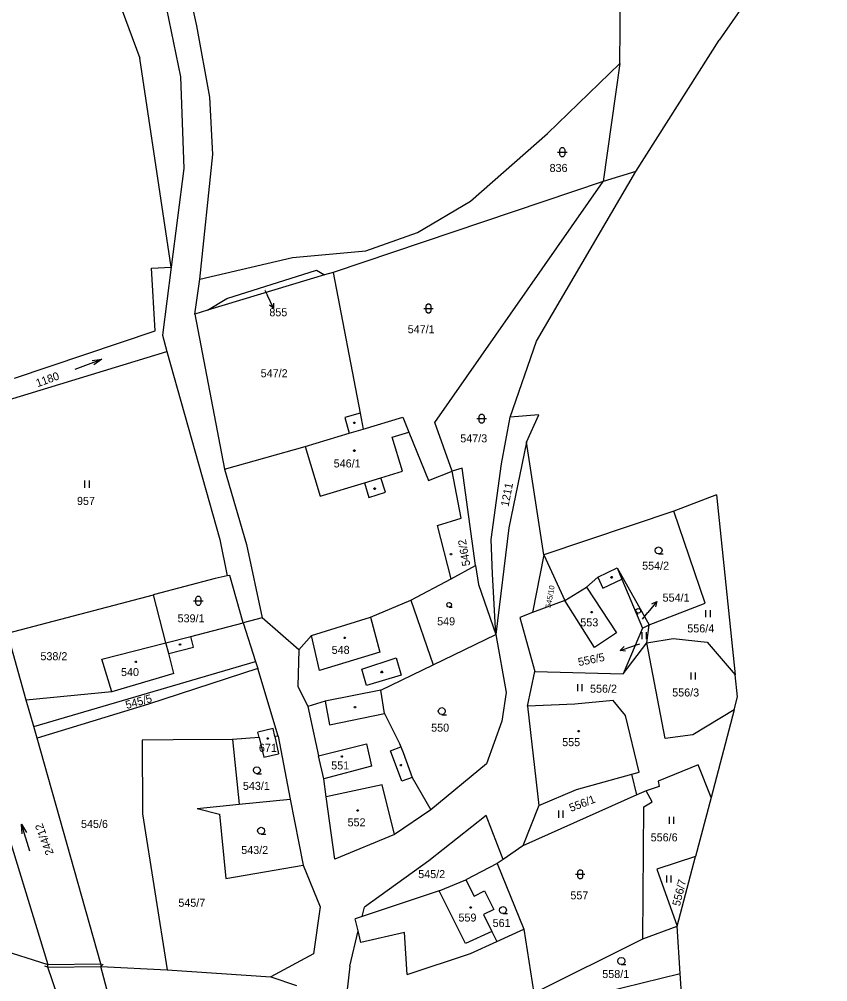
# Model space of a CAD drawing. Extents: x -812394 to -807601, y -1013097 to -1009266.
# Drawn here: x -809003.5 to -808832.6, y -1011690.8 to -1011487.2 of the extents above; entities that cross this region are included whole.
import ezdxf

# ---------------------------------------------------------------- set-up
doc = ezdxf.new("R2010")
doc.units = 0
for name, color, linetype in [('Default', 7, 'Continuous'), ('KN_HRANICE', 7, 'Continuous'), ('KN_KULTURY', 7, 'Continuous'), ('KN_PARCELY', 7, 'Continuous'), ('KN_SLUCKY', 7, 'Continuous')]:
    doc.layers.add(name, color=color, linetype=linetype)

# ---------------------------------------------------------------- blocks, each defined once
blk = doc.blocks.new('10292')
at = {"layer": 'Default'}
blk.add_line((0, 3), (0, 0), dxfattribs=at)
blk.add_lwpolyline([(-0.5, 2), (0, 3), (0.5, 2)], dxfattribs=at)
blk = doc.blocks.new('4201')
at = {"layer": 'Default'}
blk.add_line((0, 0), (-0.5, -0.5), dxfattribs=at)
blk = doc.blocks.new('304')
at = {"layer": 'Default'}
blk.add_lwpolyline([(0, 0), (-0.38, 0.1), (-0.65, 0.37), (-0.75, 0.74), (-0.65, 1.11), (-0.38, 1.38), (-0.01, 1.48), (0.36, 1.38), (0.63, 1.11), (0.73, 0.73), (0.63, 0.35), (0.36, 0.08), (-0.02, -0.02), (0.98, -0.02)], dxfattribs=at)
blk = doc.blocks.new('306')
at = {"layer": 'Default'}
for p, q in [((-0.5, 1.5), (-0.5, 0)), ((0.5, 0), (0.5, 1.5))]:
    blk.add_line(p, q, dxfattribs=at)
blk = doc.blocks.new('316')
at = {"layer": 'Default'}
for points in [[(-1, 1), (0.27, 1), (1, 1)], [(-0.5, 1.5), (-0.4, 1.79), (-0.15, 1.97), (0.16, 1.97), (0.41, 1.79), (0.51, 1.5), (0.51, 0.5), (0.41, 0.21), (0.16, 0.03), (-0.15, 0.03), (-0.4, 0.21), (-0.5, 0.5), (-0.5, 1.5)]]:
    blk.add_lwpolyline(points, dxfattribs=at)
blk = doc.blocks.new('NAHRADNI_SYMBOL')
at = {"layer": 'Default'}
blk.add_lwpolyline([(0.09, 0.15), (0.18, 0), (0.09, -0.15), (-0.09, -0.15), (-0.18, 0), (-0.09, 0.15), (0.09, 0.15)], dxfattribs=at)
blk = doc.blocks.new('802')
at = {"layer": 'Default'}
blk.add_line((-3, 0), (3, 0), dxfattribs=at)
blk.add_lwpolyline([(1, 0.5), (3, 0), (1, -0.5)], dxfattribs=at)
blk = doc.blocks.new('402')
at = {"layer": 'Default'}
blk.add_lwpolyline([(0.09, 0.15), (0.18, 0), (0.09, -0.15), (-0.09, -0.15), (-0.18, 0), (-0.09, 0.15), (0.09, 0.15)], dxfattribs=at)

msp = doc.modelspace()

# ---------------------------------------------------------------- linework, layer by layer
at = {"layer": 'KN_HRANICE'}
for p, q in [((-808965.96, -1011488.59), (-808970.28, -1011469.05)), ((-808974.44, -1011475.12), (-808969.45, -1011499.37)), ((-808963.26, -1011503.69), (-808965.96, -1011488.59)), ((-808873.2, -1011519.41), (-808855.58, -1011491.65)), ((-808971.42, -1011539.63), (-808978.04, -1011495.45)), ((-808891.84, -1011511.36), (-808876.58, -1011496.57)), ((-808876.58, -1011496.57), (-808880.08, -1011521.57)), ((-808969.45, -1011499.37), (-808968.75, -1011518.78)), ((-808962.56, -1011515.81), (-808963.26, -1011503.69)), ((-808908.15, -1011525.71), (-808891.84, -1011511.36)), ((-808965.32, -1011542.2), (-808962.56, -1011515.81)), ((-808968.75, -1011518.78), (-808971.42, -1011539.63)), ((-808894.18, -1011555.33), (-808873.2, -1011519.41)), ((-808873.2, -1011519.41), (-808880.08, -1011521.57)), ((-808880.08, -1011521.57), (-808937.15, -1011540.75)), ((-808915.66, -1011572.49), (-808880.08, -1011521.57)), ((-808919.33, -1011532.32), (-808908.15, -1011525.71)), ((-808930.24, -1011536.22), (-808919.33, -1011532.32)), ((-808945.75, -1011537.6), (-808930.24, -1011536.22)), ((-808965.32, -1011542.2), (-808945.75, -1011537.6)), ((-808975.53, -1011539.84), (-808971.42, -1011539.63)), ((-808974.75, -1011553.11), (-808975.53, -1011539.84)), ((-808971.42, -1011539.63), (-808973.26, -1011554.04)), ((-808966.39, -1011549.59), (-808965.32, -1011542.2)), ((-808939.01, -1011541.31), (-808963.72, -1011548.78)), ((-808937.15, -1011540.75), (-808939.01, -1011541.31)), ((-808937.15, -1011540.75), (-808931.47, -1011570.52)), ((-808963.72, -1011548.78), (-808966.39, -1011549.59)), ((-808966.39, -1011549.59), (-808960.16, -1011582.4)), ((-809004.54, -1011563.13), (-808974.75, -1011553.11)), ((-808973.26, -1011554.04), (-808972.29, -1011557.49)), ((-808899.78, -1011571.39), (-808894.18, -1011555.33)), ((-809001.64, -1011566.41), (-808972.29, -1011557.49)), ((-808972.29, -1011557.49), (-808961.13, -1011597.23)), ((-809019.32, -1011571.78), (-809001.64, -1011566.41)), ((-808931.47, -1011570.52), (-808934.7, -1011571.43)), ((-808931.47, -1011570.52), (-808930.83, -1011573.88)), ((-808893.7, -1011570.91), (-808899.78, -1011571.39)), ((-808896.31, -1011576.65), (-808893.7, -1011570.91)), ((-808934.7, -1011571.43), (-808933.76, -1011574.76)), ((-808930.83, -1011573.88), (-808922.44, -1011571.37)), ((-808922.44, -1011571.37), (-808921.16, -1011574.54)), ((-808911.99, -1011582.79), (-808915.66, -1011572.49)), ((-808901.58, -1011581.26), (-808899.78, -1011571.39)), ((-808943.1, -1011577.55), (-808933.76, -1011574.76)), ((-808921.16, -1011574.54), (-808917.01, -1011584.77)), ((-808896.31, -1011576.65), (-808900.05, -1011594.78)), ((-808892.65, -1011600.49), (-808896.31, -1011576.65)), ((-808960.16, -1011582.4), (-808943.1, -1011577.55)), ((-808903.77, -1011597.26), (-808901.58, -1011581.26)), ((-808960.16, -1011582.4), (-808955.5, -1011598.34)), ((-808917.01, -1011584.77), (-808911.99, -1011582.79)), ((-808909.89, -1011582.19), (-808911.99, -1011582.79)), ((-808910.08, -1011592.77), (-808911.99, -1011582.79)), ((-808907.08, -1011602.78), (-808909.89, -1011582.19)), ((-808856.13, -1011587.82), (-808865.17, -1011591.23)), ((-808856.13, -1011587.82), (-808852.21, -1011625.86)), ((-808865.17, -1011591.23), (-808892.65, -1011600.49)), ((-808858.54, -1011610.68), (-808865.17, -1011591.23)), ((-808915.15, -1011594.3), (-808910.08, -1011592.77)), ((-808912.24, -1011605.55), (-808915.15, -1011594.3)), ((-808900.05, -1011594.78), (-808902.81, -1011617.34)), ((-808961.13, -1011597.23), (-808959.58, -1011604.96)), ((-808903.49, -1011604.54), (-808903.77, -1011597.26)), ((-808955.5, -1011598.34), (-808952.16, -1011613.79)), ((-808892.65, -1011600.49), (-808895.03, -1011612.7)), ((-808892.65, -1011600.49), (-808888.21, -1011610.12)), ((-808912.24, -1011605.55), (-808907.08, -1011602.78)), ((-808907.08, -1011602.78), (-808906.47, -1011606.8)), ((-808881.24, -1011605.2), (-808877.14, -1011603.27)), ((-808877.14, -1011603.27), (-808870.36, -1011615.27)), ((-808877.14, -1011603.27), (-808876.15, -1011605.63)), ((-808962.09, -1011605.51), (-808974.9, -1011608.87)), ((-808959.58, -1011604.96), (-808962.09, -1011605.51)), ((-808959, -1011604.83), (-808959.58, -1011604.96)), ((-808956.17, -1011614.89), (-808959, -1011604.83)), ((-808920.72, -1011610.1), (-808912.24, -1011605.55)), ((-808902.81, -1011617.34), (-808903.49, -1011604.54)), ((-808883.6, -1011607.34), (-808881.24, -1011605.2)), ((-808876.15, -1011605.63), (-808871.82, -1011615.97)), ((-808906.47, -1011606.8), (-808902.81, -1011617.34)), ((-808888.21, -1011610.12), (-808883.6, -1011607.34)), ((-809006.01, -1011617.04), (-808975.11, -1011608.93)), ((-808974.9, -1011608.87), (-808975.11, -1011608.93)), ((-808972.5, -1011619.08), (-808975.11, -1011608.93)), ((-808929.24, -1011613.67), (-808920.72, -1011610.1)), ((-808920.72, -1011610.1), (-808916.02, -1011623.74)), ((-808888.21, -1011610.12), (-808895.03, -1011612.7)), ((-808870.36, -1011615.27), (-808858.54, -1011610.68)), ((-808952.16, -1011613.79), (-808956.17, -1011614.89)), ((-808944.42, -1011620.59), (-808952.16, -1011613.79)), ((-808941.71, -1011617.53), (-808929.24, -1011613.67)), ((-808895.03, -1011612.7), (-808897.71, -1011613.71)), ((-808897.71, -1011613.71), (-808894.56, -1011625.13)), ((-808967.27, -1011617.74), (-808956.17, -1011614.89)), ((-808956.17, -1011614.89), (-808953.55, -1011623.03)), ((-808871.82, -1011615.97), (-808875.9, -1011625.68)), ((-808871.82, -1011615.97), (-808870.36, -1011615.27)), ((-808870.85, -1011619.12), (-808870.36, -1011615.27)), ((-809002.01, -1011631.2), (-809006.01, -1011617.04)), ((-808972.5, -1011619.08), (-808967.27, -1011617.74)), ((-808941.71, -1011617.53), (-808944.42, -1011620.59)), ((-808916.02, -1011623.74), (-808902.81, -1011617.34)), ((-808902.81, -1011617.34), (-808900.58, -1011629.58)), ((-808986.05, -1011622.56), (-808972.5, -1011619.08)), ((-808875.9, -1011625.68), (-808870.85, -1011619.12)), ((-808870.85, -1011619.12), (-808865.28, -1011618.21)), ((-808866.98, -1011639.31), (-808870.85, -1011619.12)), ((-808865.28, -1011618.21), (-808858.15, -1011618.94)), ((-808858.15, -1011618.94), (-808852.21, -1011625.86)), ((-808944.42, -1011620.59), (-808944.61, -1011628.26)), ((-809000.43, -1011636.79), (-808953.55, -1011623.03)), ((-808983.95, -1011629.44), (-808986.05, -1011622.56)), ((-808953.55, -1011623.03), (-808953.09, -1011624.56)), ((-808927.11, -1011629.12), (-808916.02, -1011623.74)), ((-808953.09, -1011624.56), (-808976.16, -1011632.06)), ((-808948.82, -1011638.83), (-808953.09, -1011624.56)), ((-808896.11, -1011632.48), (-808894.56, -1011625.13)), ((-808894.56, -1011625.13), (-808875.9, -1011625.68)), ((-808851.7, -1011630.55), (-808852.21, -1011625.86)), ((-808944.61, -1011628.26), (-808942.49, -1011632.58)), ((-809015.5, -1011628.37), (-808997.45, -1011687.11)), ((-808983.95, -1011629.44), (-809002.01, -1011631.2)), ((-808927.11, -1011629.12), (-808938.89, -1011631.46)), ((-808926.34, -1011634.03), (-808927.11, -1011629.12)), ((-808900.58, -1011629.58), (-808901.53, -1011635.69)), ((-809000.43, -1011636.79), (-809002.01, -1011631.2)), ((-808976.16, -1011632.06), (-808999.74, -1011639.23)), ((-808938.89, -1011631.46), (-808942.49, -1011632.58)), ((-808886.06, -1011632.1), (-808896.11, -1011632.48)), ((-808877.99, -1011631.31), (-808886.06, -1011632.1)), ((-808875.36, -1011634.48), (-808877.99, -1011631.31)), ((-808852.42, -1011633.29), (-808851.7, -1011630.55)), ((-808942.49, -1011632.58), (-808940.26, -1011643.02)), ((-808926.34, -1011634.03), (-808923.15, -1011640.39)), ((-808896.11, -1011632.48), (-808893.67, -1011653.49)), ((-808852.42, -1011633.29), (-808861.12, -1011638.59)), ((-808852.42, -1011633.29), (-808857.31, -1011651.79)), ((-808901.53, -1011635.69), (-808904.76, -1011644.68)), ((-808872.48, -1011646.42), (-808875.36, -1011634.48)), ((-808999.74, -1011639.23), (-809000.43, -1011636.79)), ((-808949.87, -1011637.24), (-808953.07, -1011637.96)), ((-808952.81, -1011639.12), (-808953.07, -1011637.96)), ((-808949.52, -1011638.88), (-808949.87, -1011637.24)), ((-808986.27, -1011686.97), (-808999.74, -1011639.23)), ((-808970.95, -1011639.63), (-808977.55, -1011639.69)), ((-808977.55, -1011639.69), (-808977.45, -1011655.27)), ((-808958.46, -1011639.52), (-808970.95, -1011639.63)), ((-808952.81, -1011639.12), (-808958.46, -1011639.52)), ((-808958.46, -1011639.52), (-808957.03, -1011653.25)), ((-808952.81, -1011639.12), (-808951.84, -1011643.29)), ((-808948.82, -1011638.83), (-808949.52, -1011638.88)), ((-808949.52, -1011638.88), (-808948.71, -1011642.58)), ((-808948.82, -1011638.83), (-808946.22, -1011652.17)), ((-808923.15, -1011640.39), (-808922.85, -1011641.1)), ((-808861.12, -1011638.59), (-808866.98, -1011639.31)), ((-808922.85, -1011641.1), (-808922.34, -1011642.28)), ((-808922.34, -1011642.28), (-808920.49, -1011647.59)), ((-808951.84, -1011643.29), (-808948.71, -1011642.58)), ((-808939.13, -1011647.83), (-808940.26, -1011643.02)), ((-808904.76, -1011644.68), (-808916.52, -1011654.39)), ((-808874.08, -1011646.85), (-808872.48, -1011646.42)), ((-808860.02, -1011644.93), (-808868.49, -1011648.39)), ((-808857.31, -1011651.79), (-808860.02, -1011644.93)), ((-808938.61, -1011651.69), (-808939.13, -1011647.83)), ((-808920.49, -1011647.59), (-808916.52, -1011654.39)), ((-808885.73, -1011650.13), (-808874.08, -1011646.85)), ((-808872.98, -1011651.23), (-808874.08, -1011646.85)), ((-808868.49, -1011648.39), (-808868.26, -1011649.51)), ((-808926.82, -1011649.1), (-808938.61, -1011651.69)), ((-808924.23, -1011659.63), (-808926.82, -1011649.1)), ((-808893.67, -1011653.49), (-808885.73, -1011650.13)), ((-808871.05, -1011650.4), (-808872.98, -1011651.23)), ((-808868.26, -1011649.51), (-808871.05, -1011650.4)), ((-808869.78, -1011652.71), (-808871.05, -1011650.4)), ((-808957.03, -1011653.25), (-808946.22, -1011652.17)), ((-808946.22, -1011652.17), (-808943.5, -1011666.11)), ((-808936.84, -1011664.82), (-808938.61, -1011651.69)), ((-808872.98, -1011651.23), (-808897.06, -1011662.04)), ((-808857.31, -1011651.79), (-808860.61, -1011664.31)), ((-808965.93, -1011654.13), (-808957.03, -1011653.25)), ((-808965.93, -1011654.13), (-808961.16, -1011655.32)), ((-808916.52, -1011654.39), (-808924.23, -1011659.63)), ((-808893.67, -1011653.49), (-808897.06, -1011662.04)), ((-808871.71, -1011681.7), (-808871.48, -1011653.76)), ((-808871.48, -1011653.76), (-808869.78, -1011652.71)), ((-808977.45, -1011655.27), (-808972.23, -1011688.25)), ((-808961.16, -1011655.32), (-808959.88, -1011668.96)), ((-808904.82, -1011655.59), (-808916.94, -1011665.21)), ((-808901.27, -1011664.95), (-808904.82, -1011655.59)), ((-808924.23, -1011659.63), (-808936.84, -1011664.82)), ((-808897.06, -1011662.04), (-808901.27, -1011664.95)), ((-808860.61, -1011664.31), (-808868.75, -1011667)), ((-808864.5, -1011679.01), (-808860.61, -1011664.31)), ((-808959.88, -1011668.96), (-808943.5, -1011666.11)), ((-808943.5, -1011666.11), (-808939.94, -1011674.92)), ((-808916.94, -1011665.21), (-808930.55, -1011674.98)), ((-808902.48, -1011665.78), (-808909.14, -1011669.19)), ((-808901.27, -1011664.95), (-808902.48, -1011665.78)), ((-808902.48, -1011665.78), (-808896.85, -1011679.68)), ((-808868.75, -1011667), (-808864.5, -1011679.01)), ((-808914.74, -1011671.58), (-808909.14, -1011669.19)), ((-808909.14, -1011669.19), (-808907.39, -1011672.67)), ((-808914.74, -1011671.58), (-808931.05, -1011676.97)), ((-808907.39, -1011672.67), (-808905.21, -1011671.57)), ((-808905.21, -1011671.57), (-808903.24, -1011675.49)), ((-808939.94, -1011674.92), (-808941.31, -1011684.84)), ((-808931.05, -1011676.97), (-808930.55, -1011674.98)), ((-808931.05, -1011676.97), (-808932.49, -1011677.45)), ((-808903.24, -1011675.49), (-808905.42, -1011676.59)), ((-808905.42, -1011676.59), (-808903.63, -1011680.15)), ((-808931.89, -1011680.04), (-808932.49, -1011677.45)), ((-808871.71, -1011681.7), (-808864.5, -1011679.01)), ((-808863.84, -1011689.06), (-808864.5, -1011679.01)), ((-808933.67, -1011687.5), (-808931.89, -1011680.04)), ((-808931.32, -1011682.47), (-808931.89, -1011680.04)), ((-808922.12, -1011680.38), (-808931.32, -1011682.47)), ((-808921.53, -1011689.24), (-808922.12, -1011680.38)), ((-808903.63, -1011680.15), (-808902.57, -1011682.28)), ((-808902.57, -1011682.28), (-808896.85, -1011679.68)), ((-808896.85, -1011679.68), (-808894.75, -1011693.18)), ((-809014.11, -1011681.87), (-808997.45, -1011687.11)), ((-808908.14, -1011684.83), (-808902.57, -1011682.28)), ((-808894.75, -1011693.18), (-808871.71, -1011681.7)), ((-808941.31, -1011684.84), (-808950.35, -1011689.74)), ((-808921.53, -1011689.24), (-808908.14, -1011684.83)), ((-808997.45, -1011687.11), (-808986.27, -1011686.97)), ((-808997.44, -1011687.71), (-808997.45, -1011687.11)), ((-808986.27, -1011686.97), (-808986.26, -1011687.57)), ((-808995.44, -1011693.68), (-808997.44, -1011687.71)), ((-808986.26, -1011687.57), (-808972.23, -1011688.25)), ((-808984.63, -1011693.65), (-808986.26, -1011687.57)), ((-808972.23, -1011688.25), (-808950.35, -1011689.74)), ((-808933.67, -1011687.5), (-808934.28, -1011693.03)), ((-808879.89, -1011692.95), (-808863.84, -1011689.06)), ((-808861.85, -1011719.28), (-808863.84, -1011689.06)), ((-808950.35, -1011689.74), (-808944.94, -1011691.54))]:
    msp.add_line(p, q, dxfattribs=at)
for points in [[(-808876.58, -1011496.57), (-808876.5, -1011489.14), (-808876.71, -1011462.42), (-808881.55, -1011440.6), (-808894.69, -1011432.01), (-808924.68, -1011432.91), (-808919.61, -1011417.84), (-808910.04, -1011399.6), (-808897.42, -1011390.94), (-808865.7, -1011380.51), (-808873.42, -1011358.96)], [(-809039.69, -1011388.93), (-809024.1, -1011392.16), (-809015.94, -1011401.01), (-809005.51, -1011425.71), (-808989.67, -1011464.02), (-808978.04, -1011495.45)], [(-808777.29, -1011424.22), (-808793.61, -1011431.29), (-808814.66, -1011442.69), (-808827.8, -1011455.19), (-808842.35, -1011472.52), (-808855.58, -1011491.65)], [(-808963.72, -1011548.78), (-808959.65, -1011546.28), (-808940.7, -1011540.29), (-808939.01, -1011541.31)]]:
    msp.add_lwpolyline(points, dxfattribs=at)
at = {"layer": 'KN_PARCELY'}
for p, q in [((-808951.59, -1011544.55), (-808951.07, -1011545.65)), ((-808871.82, -1011614.11), (-808870.68, -1011612.71)), ((-808872.46, -1011619.39), (-808873.64, -1011619.77))]:
    msp.add_line(p, q, dxfattribs=at)
at = {"layer": 'KN_SLUCKY'}
for p, q in [((-808933.76, -1011574.76), (-808930.83, -1011573.88)), ((-808924.71, -1011575.62), (-808921.16, -1011574.54)), ((-808922.53, -1011582.8), (-808924.71, -1011575.62)), ((-808943.1, -1011577.55), (-808939.94, -1011588.09)), ((-808927.09, -1011584.18), (-808922.53, -1011582.8)), ((-808939.94, -1011588.09), (-808930.53, -1011585.23)), ((-808930.53, -1011585.23), (-808927.09, -1011584.18)), ((-808930.53, -1011585.23), (-808929.61, -1011588.4)), ((-808926.07, -1011587.22), (-808927.09, -1011584.18)), ((-808929.61, -1011588.4), (-808926.07, -1011587.22)), ((-808881.24, -1011605.2), (-808880.15, -1011607.51)), ((-808880.15, -1011607.51), (-808876.15, -1011605.63)), ((-808883.6, -1011607.34), (-808877.26, -1011617.01)), ((-808881.92, -1011620.12), (-808888.21, -1011610.12)), ((-808929.24, -1011613.67), (-808927.28, -1011621.11)), ((-808966.69, -1011620.05), (-808967.27, -1011617.74)), ((-808940.08, -1011624.95), (-808941.71, -1011617.53)), ((-808877.26, -1011617.01), (-808881.92, -1011620.12)), ((-808971.91, -1011621.37), (-808972.5, -1011619.08)), ((-808971.91, -1011621.37), (-808966.69, -1011620.05)), ((-808970.84, -1011625.57), (-808971.91, -1011621.37)), ((-808927.28, -1011621.11), (-808940.08, -1011624.95)), ((-808931.14, -1011624.64), (-808923.87, -1011622.27)), ((-808923.87, -1011622.27), (-808922.78, -1011625.91)), ((-808970.84, -1011625.57), (-808983.95, -1011629.44)), ((-808930.11, -1011628.1), (-808931.14, -1011624.64)), ((-808922.78, -1011625.91), (-808930.11, -1011628.1)), ((-808938.89, -1011631.46), (-808937.94, -1011636.42)), ((-808937.94, -1011636.42), (-808926.34, -1011634.03)), ((-808940.26, -1011643.02), (-808930.1, -1011640.49)), ((-808930.1, -1011640.49), (-808929.06, -1011645.16)), ((-808925.04, -1011641.91), (-808922.85, -1011641.1)), ((-808922.67, -1011648.35), (-808925.04, -1011641.91)), ((-808929.06, -1011645.16), (-808939.13, -1011647.83)), ((-808920.49, -1011647.59), (-808922.67, -1011648.35)), ((-808909.19, -1011682.69), (-808914.74, -1011671.58)), ((-808903.63, -1011680.15), (-808909.19, -1011682.69)), ((-808997.44, -1011687.71), (-808986.26, -1011687.57))]:
    msp.add_line(p, q, dxfattribs=at)

# ---------------------------------------------------------------- block references
at = {"layer": 'KN_KULTURY'}
for name, p in [('316', (-808888.73, -1011516.33)), ('316', (-808917.01, -1011549.41)), ('316', (-808905.78, -1011572.69)), ('402', (-808932.7, -1011572.58)), ('402', (-808932.71, -1011578.46)), ('306', (-808989.19, -1011586.3)), ('402', (-808928.41, -1011586.49)), ('304', (-808868.4, -1011600.29)), ('NAHRADNI_SYMBOL', (-808912.27, -1011600.35)), ('402', (-808878.33, -1011605.25)), ('316', (-808965.66, -1011611.21)), ('402', (-808882.54, -1011612.61)), ('306', (-808857.95, -1011613.7)), ('402', (-808934.71, -1011618.05)), ('306', (-808871.45, -1011618.36)), ('402', (-808969.54, -1011619.45)), ('402', (-808978.86, -1011623.12)), ('402', (-808926.88, -1011625.27)), ('306', (-808861.1, -1011626.85)), ('306', (-808885.05, -1011629.35)), ('402', (-808932.54, -1011632.7)), ('304', (-808914.2, -1011634.28)), ('NAHRADNI_SYMBOL', (-808885.27, -1011637.77)), ('402', (-808950.98, -1011639.31)), ('402', (-808935.32, -1011643.16)), ('304', (-808953.28, -1011646.78)), ('402', (-808922.86, -1011644.95)), ('NAHRADNI_SYMBOL', (-808931.98, -1011654.57)), ('306', (-808889.07, -1011656.09)), ('306', (-808865.65, -1011657.4)), ('304', (-808952.38, -1011659.58)), ('316', (-808884.95, -1011669.06)), ('306', (-808866.25, -1011669.81)), ('402', (-808908.09, -1011675.07)), ('304', (-808901.27, -1011676.35)), ('304', (-808876.26, -1011687.13))]:
    msp.add_blockref(name, p, dxfattribs=at)
for p, rotation in [((-808988.88, -1011560.18), 20.511889), ((-809002.13, -1011660.29), 106.913925)]:
    msp.add_blockref('802', p, dxfattribs=dict(at, rotation=rotation))
at = {"layer": 'KN_KULTURY', "xscale": 0.67, "yscale": 0.67}
msp.add_blockref('304', (-808912.65, -1011611.56), dxfattribs=at)
at = {"layer": 'KN_KULTURY', "xscale": 0.67, "yscale": 0.6699999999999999, "rotation": -59.598228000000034}
msp.add_blockref('304', (-808873.1, -1011612.57), dxfattribs=at)
at = {"layer": 'KN_PARCELY'}
for p, rotation in [((-808951.07, -1011545.65), -154.30815200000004), ((-808870.68, -1011612.71), -39.25822599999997), ((-808873.64, -1011619.77), 107.830657)]:
    msp.add_blockref('10292', p, dxfattribs=dict(at, rotation=rotation))
at = {"layer": 'KN_SLUCKY'}
for p, rotation in [((-808997.44, -1011687.71), -65.90076400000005), ((-808986.26, -1011687.57), 179.33579)]:
    msp.add_blockref('4201', p, dxfattribs=dict(at, rotation=rotation))

# ---------------------------------------------------------------- texts
at = {"layer": 'KN_PARCELY'}
for s, height, p in [('836', 1.7, (-808891.43, -1011519.52)), ('855', 1.7, (-808950.65, -1011550.04)), ('547/1', 1.7, (-808921.41, -1011553.63)), ('547/2', 1.7, (-808952.48, -1011562.94)), ('547/3', 1.7, (-808910.3, -1011576.71)), ('546/1', 1.7, (-808937.05, -1011582.01)), ('957', 1.7, (-808991.3, -1011589.94)), ('554/2', 1.7, (-808871.87, -1011603.64)), ('554/1', 1.7, (-808867.54, -1011610.39)), ('539/1', 1.7, (-808970.04, -1011614.77)), ('549', 1.7, (-808915.19, -1011615.4)), ('553', 1.7, (-808884.93, -1011615.62)), ('554/1', 0.1, (-808872.05, -1011614.11)), ('556/4', 1.7, (-808862.32, -1011616.9)), ('548', 1.7, (-808937.48, -1011621.44)), ('556/5', 0.1, (-808872.7, -1011619.39)), ('538/2', 1.7, (-808999.03, -1011622.78)), ('540', 1.7, (-808982, -1011626.13)), ('556/2', 1.7, (-808882.88, -1011629.65)), ('556/3', 1.7, (-808865.51, -1011630.45)), ('550', 1.7, (-808916.46, -1011637.89)), ('671', 1.7, (-808952.86, -1011642.16)), ('555', 1.7, (-808888.77, -1011640.95)), ('551', 1.7, (-808937.58, -1011645.88)), ('543/1', 1.7, (-808956.24, -1011650.2)), ('545/6', 1.7, (-808990.45, -1011658.25)), ('552', 1.7, (-808934.12, -1011657.91)), ('556/6', 1.7, (-808870.06, -1011661.09)), ('543/2', 1.7, (-808956.59, -1011663.76)), ('545/2', 1.7, (-808919.19, -1011668.86)), ('557', 1.7, (-808887.03, -1011673.35)), ('545/7', 1.7, (-808969.88, -1011674.92)), ('559', 1.7, (-808910.68, -1011678.05)), ('561', 1.7, (-808903.46, -1011679.19)), ('558/1', 1.7, (-808880.29, -1011689.99))]:
    msp.add_text(s, height=height, dxfattribs=at).set_placement(p)
for s, height, rotation, p in [('855', 0.1, 70.13, (-808951.45, -1011544.4)), ('1180', 1.7, 20.054, (-808999.63, -1011565.06)), ('1211', 1.7, 78.954, (-808900.11, -1011590.39)), ('546/2', 1.7, 99.809, (-808908.17, -1011602.72)), ('545/10', 1.14, 79.698, (-808891.21, -1011611.81)), ('556/5', 1.7, 11.746, (-808885.23, -1011624.04)), ('545/5', 1.7, 15.584, (-808980.79, -1011633.11)), ('556/1', 1.7, 21.314, (-808886.89, -1011654.88)), ('244/12', 1.7, 110.695, (-808996.19, -1011663.64)), ('556/7', 1.7, 75.974, (-808863.9, -1011674.9))]:
    msp.add_text(s, height=height, rotation=rotation, dxfattribs=at).set_placement(p)

doc.saveas('drawing.dxf')
